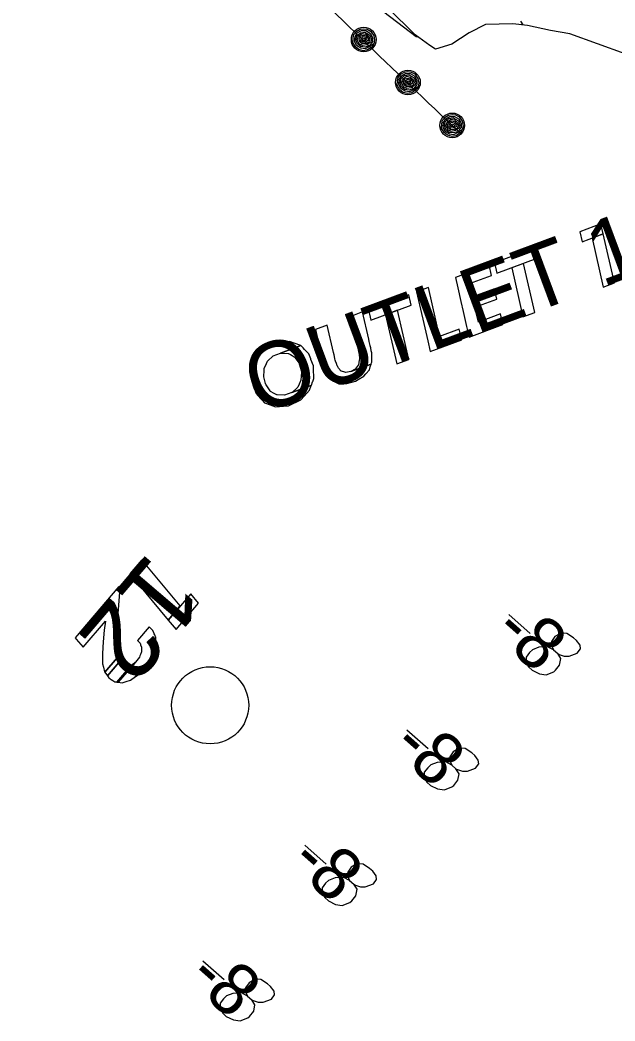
# Model space of a CAD drawing. Extents: x 3962991 to 3983549, y 181631 to 204078.
# Drawn here: x 3977570 to 3977956, y 190147 to 190796 of the extents above; entities that cross this region are included whole.
import ezdxf

# ---------------------------------------------------------------- set-up
doc = ezdxf.new("R2010")
doc.units = 0
for name, color, linetype in [('V-ANNO-MASK', 7, 'Continuous'), ('V-ANNO-MASK2', 7, 'Continuous'), ('V-RIVR-EDGE', 7, 'Continuous'), ('V-RIVR-IDEN', 7, 'Continuous'), ('V-RIVR-MILE', 7, 'Continuous'), ('V-RIVR-RANG', 7, 'Continuous'), ('V-RRAP-FSHR', 7, 'Continuous'), ('V-WETL-SWMP', 7, 'Continuous')]:
    doc.layers.add(name, color=color, linetype=linetype)

msp = doc.modelspace()

# ---------------------------------------------------------------- linework, layer by layer
at = {"layer": 'V-ANNO-MASK2'}
for p, q in [((3977887.31, 190410.64), (3977901.14, 190398.41)), ((3977821.27, 190335.95), (3977835.1, 190323.72)), ((3977755.04, 190261.03), (3977768.87, 190248.8)), ((3977688.8, 190186.11), (3977702.64, 190173.88))]:
    msp.add_line(p, q, dxfattribs=at)
for points in [[(3977933.53, 190659.01), (3977935.02, 190652.5), (3977948.62, 190657.56), (3977947.13, 190664.07)], [(3977941.36, 190654.87), (3977948.64, 190623.08), (3977955.89, 190625.78), (3977948.62, 190657.56)], [(3977878.15, 190638.82), (3977879.69, 190632.05), (3977905.84, 190641.77), (3977904.29, 190648.55)], [(3977859.98, 190597.52), (3977861.55, 190590.68), (3977883.45, 190598.83), (3977881.88, 190605.66), (3977867.62, 190600.36), (3977865.4, 190610), (3977879.67, 190615.31), (3977878.14, 190621.98), (3977863.87, 190616.67), (3977861.88, 190625.37), (3977876.15, 190630.68), (3977874.59, 190637.5), (3977852.69, 190629.35), (3977854.25, 190622.53), (3977856.24, 190613.83), (3977857.77, 190607.16)], [(3977889.24, 190635.6), (3977896.56, 190603.71), (3977904.27, 190606.58), (3977896.96, 190638.47)], [(3977796.37, 190608.4), (3977797.92, 190601.63), (3977824.06, 190611.36), (3977822.52, 190618.13)], [(3977834.79, 190588.2), (3977836.38, 190581.32), (3977856.83, 190588.93), (3977855.25, 190595.81), (3977842.5, 190591.07), (3977835.23, 190622.85), (3977827.52, 190619.99)], [(3977787.71, 190569.92), (3977784.87, 190568.26), (3977798.13, 190573.19), (3977798.36, 190573.88), (3977798.37, 190573.91), (3977798.55, 190574.44), (3977798.54, 190575.85), (3977798.55, 190575.97), (3977798.54, 190576.01), (3977798.53, 190578.67), (3977798.53, 190579.53), (3977798.53, 190579.78), (3977798.41, 190580.37), (3977798.12, 190581.85), (3977798.11, 190581.85), (3977797.76, 190583.61), (3977797.62, 190584.28), (3977797.46, 190585.07), (3977797.44, 190585.2), (3977796.86, 190587.73), (3977796.51, 190589.26), (3977792.46, 190606.95), (3977784.8, 190604.1), (3977788.8, 190586.4), (3977789.15, 190584.86), (3977789.71, 190582.32), (3977789.73, 190582.2), (3977789.9, 190581.4), (3977790.06, 190580.74), (3977790.27, 190578.93), (3977790.45, 190577.41), (3977790.52, 190576.8), (3977790.55, 190576.57), (3977790.36, 190575.63), (3977789.79, 190572.75), (3977789.78, 190572.71), (3977789.66, 190572.54), (3977788.29, 190570.62), (3977787.85, 190569.99)], [(3977807.47, 190605.18), (3977814.78, 190573.29), (3977822.5, 190576.16), (3977815.19, 190608.06)], [(3977782.34, 190560.46), (3977787.86, 190562.15), (3977789.71, 190563.21), (3977793.23, 190565.21), (3977794.65, 190566.87), (3977796.89, 190569.5), (3977797.51, 190571.35), (3977798.13, 190573.19), (3977784.87, 190568.26), (3977781.65, 190567.66), (3977781.61, 190567.67), (3977780.92, 190567.88), (3977778.81, 190568.51), (3977778.72, 190568.59), (3977778.7, 190568.63), (3977776.77, 190570.57), (3977776.44, 190571.32), (3977776.35, 190571.53), (3977776.1, 190572.07), (3977775.5, 190573.44), (3977775, 190575.14), (3977774.81, 190575.79), (3977774.59, 190576.57), (3977774.56, 190576.69), (3977773.99, 190579.22), (3977773.63, 190580.76), (3977769.59, 190598.44), (3977761.88, 190595.57), (3977765.93, 190577.89), (3977766.29, 190576.36), (3977766.91, 190573.84), (3977766.94, 190573.72), (3977767.13, 190572.93), (3977767.32, 190572.28), (3977767.81, 190570.58), (3977768.23, 190569.15), (3977768.49, 190568.6), (3977768.59, 190568.4), (3977768.94, 190567.66), (3977770.03, 190565.4), (3977770.05, 190565.37), (3977770.14, 190565.28), (3977771.12, 190564.23), (3977771.43, 190563.89), (3977771.45, 190563.87), (3977771.87, 190563.43), (3977772.99, 190562.23), (3977774.96, 190561.34), (3977777.16, 190560.37), (3977780.37, 190560.42)], [(3977741.27, 190545.83), (3977744.35, 190546.09), (3977752.43, 190549.97), (3977754.51, 190552.27), (3977758.02, 190556.13), (3977759.23, 190559.36), (3977746.65, 190554.68), (3977741.83, 190552.94), (3977737.02, 190553.14), (3977736.91, 190553.19), (3977735.08, 190554.18), (3977735.07, 190554.18), (3977732.74, 190555.43), (3977732.52, 190555.74), (3977731.62, 190557.06), (3977729.89, 190559.59), (3977729.82, 190559.87), (3977729.81, 190559.87), (3977729.62, 190560.56), (3977728.45, 190564.79), (3977728.45, 190564.79), (3977728.43, 190564.87), (3977728.45, 190565.16), (3977728.65, 190568.98), (3977728.72, 190570.29), (3977728.73, 190570.32), (3977730.14, 190573.53), (3977730.79, 190575), (3977730.82, 190575.07), (3977734.54, 190578.46), (3977734.57, 190578.49), (3977739.35, 190580.3), (3977752.43, 190585.16), (3977748.21, 190586.74), (3977745.17, 190587.88), (3977739.57, 190587.39), (3977737.05, 190587.18), (3977737.05, 190587.18), (3977729.28, 190583.57), (3977726.87, 190581.07), (3977723.47, 190577.54), (3977722.06, 190573.86), (3977722.04, 190573.83), (3977722.04, 190573.81), (3977721.14, 190571.47), (3977721.11, 190571.4), (3977720.56, 190569.96), (3977720.55, 190567.27), (3977720.55, 190567.24), (3977720.55, 190565.97), (3977720.54, 190562.22), (3977720.53, 190561.93), (3977720.54, 190561.85), (3977722.02, 190557.73), (3977722.26, 190557.06), (3977722.37, 190556.79), (3977723.38, 190554), (3977724.51, 190552.76), (3977724.79, 190552.47), (3977726.24, 190550.89), (3977727.4, 190549.65), (3977727.46, 190549.58), (3977728.83, 190548.11), (3977728.9, 190548.08), (3977732.59, 190546.67), (3977735.98, 190545.38)], [(3977746.75, 190554.77), (3977746.65, 190554.68), (3977759.23, 190559.36), (3977759.26, 190559.43), (3977759.25, 190559.42), (3977760.11, 190561.73), (3977760.16, 190561.84), (3977760.15, 190561.84), (3977760.88, 190563.78), (3977760.82, 190565.87), (3977760.81, 190566.26), (3977760.8, 190566.26), (3977760.76, 190567.9), (3977760.66, 190571.03), (3977760.65, 190571.34), (3977760.63, 190572.09), (3977759.03, 190576.17), (3977759, 190576.24), (3977758.91, 190576.49), (3977757.63, 190579.76), (3977756.73, 190580.7), (3977756.71, 190580.72), (3977754.81, 190582.71), (3977753.94, 190583.62), (3977753.9, 190583.66), (3977752.49, 190585.14), (3977752.47, 190585.15), (3977752.43, 190585.16), (3977739.35, 190580.3), (3977739.42, 190580.29), (3977739.45, 190580.29), (3977744.3, 190580.08), (3977744.43, 190580.08), (3977745.72, 190579.32), (3977748.54, 190577.68), (3977748.56, 190577.66), (3977749.26, 190576.65), (3977751.34, 190573.67), (3977751.41, 190573.41), (3977751.43, 190573.34), (3977752.6, 190569.1), (3977752.79, 190568.41), (3977752.77, 190568.1), (3977752.61, 190564.87), (3977752.54, 190563.19), (3977752.34, 190562.72), (3977751.27, 190560.21), (3977750.44, 190558.23), (3977750.27, 190558.07)], [(3977674.16, 190416.26), (3977649.18, 190446.27), (3977641.41, 190437.16), (3977666.39, 190407.15)], [(3977635.14, 190427.95), (3977634.41, 190428.97), (3977605.96, 190395.65), (3977606.75, 190394.71), (3977611.12, 190389.46), (3977625.64, 190406.47), (3977624.75, 190400.46), (3977624.12, 190392.97), (3977623.72, 190385.36), (3977623.74, 190384.25), (3977623.82, 190380.17), (3977623.85, 190378.8), (3977624.4, 190376.57), (3977625.11, 190373.61), (3977625.32, 190373.29), (3977633.28, 190382.62), (3977633.22, 190383.1), (3977632.79, 190386.4), (3977632.78, 190389.26), (3977632.76, 190390.64), (3977632.94, 190395.02), (3977633.03, 190396.27), (3977633.54, 190404.01), (3977634.03, 190411.33), (3977634.39, 190416.72)], [(3977686.08, 190418.08), (3977680.97, 190424.23), (3977666.39, 190407.15), (3977671.5, 190401)], [(3977654.12, 190402.7), (3977654.09, 190402.73), (3977646.53, 190393.88), (3977646.56, 190393.85), (3977647.51, 190392.72), (3977647.52, 190392.73), (3977648.11, 190392.02), (3977648.35, 190391.46), (3977648.52, 190391.06), (3977649.11, 190389.63), (3977649.09, 190388.43), (3977649.06, 190387.49), (3977649.04, 190386.53), (3977648.34, 190384.69), (3977648.07, 190383.98), (3977647.72, 190383.05), (3977645.13, 190379.74), (3977634.03, 190366.74), (3977636.49, 190366.4), (3977639.08, 190367.22), (3977642.03, 190368.15), (3977645.26, 190370.44), (3977656.58, 190383.7), (3977657.32, 190386.06), (3977658.57, 190390.04), (3977658.48, 190392.16), (3977658.35, 190395.21), (3977658.34, 190395.48), (3977658.31, 190395.97), (3977658.2, 190396.23), (3977657.9, 190396.9), (3977657.62, 190397.52), (3977657.35, 190398.11), (3977657.01, 190398.87), (3977656.38, 190400.26), (3977656.11, 190400.55), (3977655.74, 190400.96), (3977655.12, 190401.63)], [(3977653.78, 190379.39), (3977656.58, 190383.69), (3977645.26, 190370.44), (3977647.48, 190372.01), (3977652.44, 190377.33), (3977652.45, 190377.34)], [(3977634.38, 190379.66), (3977633.28, 190382.61), (3977625.32, 190373.29), (3977626.93, 190370.93), (3977626.96, 190370.9), (3977634.41, 190379.61)], [(3977635.44, 190378.58), (3977634.4, 190379.61), (3977626.96, 190370.9), (3977627.81, 190369.65), (3977628.57, 190369.14), (3977629.02, 190368.83), (3977629.35, 190368.6), (3977629.35, 190368.61), (3977630.5, 190367.83), (3977631.13, 190367.4), (3977631.62, 190367.06), (3977632.33, 190366.97), (3977633.12, 190366.86), (3977642.21, 190377.51), (3977641.1, 190377.24), (3977640.1, 190377), (3977639.12, 190376.76), (3977638.33, 190377), (3977636.89, 190377.43), (3977636.47, 190377.55), (3977636.09, 190377.94)], [(3977643.19, 190378.25), (3977642.2, 190377.5), (3977633.12, 190366.87), (3977633.42, 190366.82), (3977633.82, 190366.77), (3977634.03, 190366.74), (3977645.14, 190379.75), (3977644.44, 190379.21)]]:
    msp.add_lwpolyline(points, close=True, dxfattribs=at)
for points in [[(3977916.37, 190387.77), (3977919.14, 190385.32), (3977920.1, 190384.82), (3977923.35, 190383.71), (3977926.52, 190383.72), (3977931.82, 190385.73), (3977933.89, 190388.47), (3977933.56, 190390.88), (3977931.32, 190393.92), (3977929.34, 190395.66), (3977925.06, 190398.39), (3977922.43, 190398.6), (3977919.5, 190397.68), (3977917.33, 190396.42), (3977915.11, 190393.11), (3977914.85, 190391.22), (3977916.37, 190387.77), (3977912.51, 190389.77), (3977906.93, 190389.43), (3977902.72, 190387.86), (3977900.78, 190386.06), (3977898.53, 190383.12), (3977898.56, 190379.57), (3977900.23, 190376.68), (3977902.61, 190374.59), (3977907.23, 190372.25), (3977911.57, 190371.59), (3977916.5, 190373.57), (3977917.74, 190374.58), (3977920.34, 190377.92), (3977921.21, 190382.08), (3977919.14, 190385.32)], [(3977850.34, 190313.07), (3977853.1, 190310.62), (3977854.07, 190310.12), (3977857.31, 190309.01), (3977860.49, 190309.02), (3977865.78, 190311.03), (3977867.86, 190313.77), (3977867.52, 190316.18), (3977865.28, 190319.22), (3977863.3, 190320.97), (3977859.03, 190323.7), (3977856.4, 190323.91), (3977853.46, 190322.98), (3977851.3, 190321.73), (3977849.07, 190318.41), (3977848.81, 190316.53), (3977850.34, 190313.07), (3977846.47, 190315.08), (3977840.89, 190314.73), (3977836.69, 190313.17), (3977834.74, 190311.36), (3977832.49, 190308.42), (3977832.53, 190304.87), (3977834.2, 190301.99), (3977836.57, 190299.89), (3977841.2, 190297.56), (3977845.54, 190296.89), (3977850.46, 190298.88), (3977851.71, 190299.89), (3977854.3, 190303.22), (3977855.17, 190307.39), (3977853.1, 190310.62)], [(3977784.1, 190238.15), (3977786.87, 190235.7), (3977787.83, 190235.2), (3977791.08, 190234.09), (3977794.25, 190234.1), (3977799.55, 190236.11), (3977801.62, 190238.85), (3977801.29, 190241.26), (3977799.05, 190244.3), (3977797.07, 190246.05), (3977792.79, 190248.78), (3977790.16, 190248.99), (3977787.23, 190248.06), (3977785.06, 190246.81), (3977782.84, 190243.49), (3977782.58, 190241.61), (3977784.1, 190238.15), (3977780.24, 190240.16), (3977774.65, 190239.81), (3977770.45, 190238.25), (3977768.51, 190236.44), (3977766.26, 190233.5), (3977766.29, 190229.95), (3977767.96, 190227.07), (3977770.34, 190224.97), (3977774.96, 190222.64), (3977779.3, 190221.97), (3977784.23, 190223.96), (3977785.47, 190224.97), (3977788.07, 190228.3), (3977788.94, 190232.47), (3977786.87, 190235.7)], [(3977717.87, 190163.23), (3977720.63, 190160.78), (3977721.6, 190160.28), (3977724.84, 190159.17), (3977728.02, 190159.18), (3977733.32, 190161.19), (3977735.39, 190163.93), (3977735.05, 190166.34), (3977732.81, 190169.38), (3977730.84, 190171.13), (3977726.56, 190173.86), (3977723.93, 190174.07), (3977720.99, 190173.14), (3977718.83, 190171.89), (3977716.6, 190168.57), (3977716.35, 190166.69), (3977717.87, 190163.23), (3977714.01, 190165.24), (3977708.42, 190164.89), (3977704.22, 190163.33), (3977702.27, 190161.52), (3977700.03, 190158.58), (3977700.06, 190155.03), (3977701.73, 190152.15), (3977704.1, 190150.05), (3977708.73, 190147.72), (3977713.07, 190147.05), (3977717.99, 190149.04), (3977719.24, 190150.05), (3977721.84, 190153.38), (3977722.7, 190157.55), (3977720.63, 190160.78)]]:
    msp.add_lwpolyline(points, dxfattribs=at)
at = {"layer": 'V-RIVR-EDGE'}
msp.add_lwpolyline([(3977597.25, 191003.12), (3977596.69, 190992.64), (3977667.63, 190915.78), (3977777, 190824.15), (3977827.25, 190785.72), (3977828.42, 190785.4)], dxfattribs=at)
at = {"layer": 'V-RIVR-MILE'}
msp.add_circle((3977693.61, 190351.82), 25, dxfattribs=at)
at = {"layer": 'V-RRAP-FSHR'}
for points in [[(3977799.76, 190780.4), (3977798.4, 190778.83), (3977795.74, 190776.92), (3977793.2, 190776.45), (3977790.08, 190777.23), (3977787.97, 190778.99), (3977786.23, 190781.82), (3977786.43, 190784.72), (3977786.81, 190786.96), (3977788.68, 190789.1), (3977790.88, 190790.36), (3977793.21, 190790.71), (3977795.41, 190790.41), (3977797.7, 190789.16), (3977799.73, 190786.34), (3977800.28, 190783.2), (3977799.75, 190780.85), (3977796.78, 190778.97), (3977794.14, 190777.62), (3977791.38, 190778.05), (3977788.64, 190779.77), (3977787.33, 190782.58), (3977787.6, 190785.59), (3977789.03, 190787.99), (3977791.72, 190789.5), (3977794.7, 190789.47), (3977797.62, 190787.65), (3977798.97, 190784.83), (3977798.99, 190782.04), (3977796.71, 190779.57), (3977794.08, 190778.74), (3977791.26, 190779.11), (3977789.1, 190780.83), (3977788.21, 190783.32), (3977788.69, 190786.04), (3977791.06, 190788.11), (3977793.86, 190788.56), (3977797.2, 190786.59), (3977798.22, 190783.93), (3977797.83, 190782.07), (3977795.36, 190780.27), (3977792.53, 190779.71), (3977790.36, 190780.83), (3977789.08, 190783.58), (3977789.83, 190785.83), (3977792.32, 190787.65), (3977794.69, 190787.19), (3977796.54, 190785.61), (3977797.31, 190783.59), (3977796.41, 190781.73), (3977794.56, 190781), (3977792.27, 190780.78), (3977790.69, 190782.14), (3977790.21, 190784.04), (3977791.25, 190785.96), (3977793.06, 190786.56), (3977794.77, 190786.09), (3977796.12, 190784.34), (3977796.02, 190783.01), (3977794.29, 190781.99), (3977792.37, 190781.9), (3977791.32, 190782.88), (3977791.48, 190784.43), (3977792.85, 190785.71), (3977794.41, 190785.22), (3977795.09, 190784.07), (3977794.03, 190782.81), (3977792.4, 190782.93), (3977792.36, 190784.11), (3977793.41, 190784.56), (3977794.14, 190784.14), (3977793.23, 190783.63)], [(3977828.48, 190752.56), (3977827.12, 190750.99), (3977824.46, 190749.08), (3977821.92, 190748.61), (3977818.81, 190749.39), (3977816.69, 190751.15), (3977814.95, 190753.98), (3977815.15, 190756.88), (3977815.53, 190759.12), (3977817.4, 190761.26), (3977819.59, 190762.52), (3977821.93, 190762.86), (3977824.12, 190762.57), (3977826.42, 190761.32), (3977828.45, 190758.49), (3977829, 190755.36), (3977828.47, 190753.01), (3977825.5, 190751.12), (3977822.85, 190749.78), (3977820.1, 190750.21), (3977817.36, 190751.93), (3977816.05, 190754.74), (3977816.32, 190757.75), (3977817.75, 190760.15), (3977820.44, 190761.66), (3977823.42, 190761.62), (3977826.34, 190759.81), (3977827.69, 190756.99), (3977827.71, 190754.2), (3977825.43, 190751.72), (3977822.8, 190750.9), (3977819.98, 190751.27), (3977817.82, 190752.99), (3977816.93, 190755.48), (3977817.41, 190758.2), (3977819.77, 190760.26), (3977822.58, 190760.72), (3977825.92, 190758.75), (3977826.94, 190756.09), (3977826.55, 190754.22), (3977824.08, 190752.43), (3977821.25, 190751.87), (3977819.08, 190752.99), (3977817.8, 190755.74), (3977818.55, 190757.99), (3977821.04, 190759.81), (3977823.41, 190759.35), (3977825.25, 190757.76), (3977826.03, 190755.75), (3977825.13, 190753.89), (3977823.28, 190753.16), (3977820.98, 190752.94), (3977819.41, 190754.3), (3977818.93, 190756.2), (3977819.97, 190758.11), (3977821.79, 190758.72), (3977823.49, 190758.25), (3977824.84, 190756.49), (3977824.74, 190755.17), (3977823.01, 190754.15), (3977821.09, 190754.06), (3977820.04, 190755.03), (3977820.2, 190756.59), (3977821.57, 190757.87), (3977823.13, 190757.38), (3977823.81, 190756.23), (3977822.75, 190754.97), (3977821.12, 190755.09), (3977821.08, 190756.27), (3977822.13, 190756.72), (3977822.86, 190756.3), (3977821.95, 190755.79)], [(3977857.2, 190724.72), (3977855.84, 190723.14), (3977853.18, 190721.24), (3977850.64, 190720.77), (3977847.52, 190721.55), (3977845.41, 190723.31), (3977843.67, 190726.14), (3977843.87, 190729.04), (3977844.25, 190731.28), (3977846.12, 190733.42), (3977848.31, 190734.68), (3977850.65, 190735.02), (3977852.85, 190734.73), (3977855.14, 190733.48), (3977857.17, 190730.65), (3977857.72, 190727.52), (3977857.19, 190725.17), (3977854.22, 190723.28), (3977851.57, 190721.94), (3977848.82, 190722.37), (3977846.08, 190724.09), (3977844.77, 190726.9), (3977845.04, 190729.91), (3977846.47, 190732.31), (3977849.16, 190733.82), (3977852.14, 190733.78), (3977855.06, 190731.97), (3977856.41, 190729.15), (3977856.43, 190726.36), (3977854.15, 190723.88), (3977851.52, 190723.06), (3977848.7, 190723.43), (3977846.54, 190725.15), (3977845.65, 190727.64), (3977846.13, 190730.36), (3977848.49, 190732.42), (3977851.3, 190732.88), (3977854.64, 190730.9), (3977855.66, 190728.25), (3977855.27, 190726.38), (3977852.79, 190724.59), (3977849.97, 190724.02), (3977847.8, 190725.15), (3977846.52, 190727.9), (3977847.27, 190730.15), (3977849.76, 190731.97), (3977852.13, 190731.51), (3977853.98, 190729.92), (3977854.75, 190727.91), (3977853.85, 190726.05), (3977852, 190725.32), (3977849.7, 190725.1), (3977848.13, 190726.46), (3977847.65, 190728.35), (3977848.69, 190730.27), (3977850.5, 190730.88), (3977852.21, 190730.41), (3977853.56, 190728.65), (3977853.46, 190727.33), (3977851.73, 190726.31), (3977849.81, 190726.21), (3977848.76, 190727.19), (3977848.92, 190728.75), (3977850.29, 190730.03), (3977851.85, 190729.54), (3977852.53, 190728.39), (3977851.47, 190727.13), (3977849.84, 190727.25), (3977849.8, 190728.43), (3977850.85, 190728.88), (3977851.58, 190728.46), (3977850.67, 190727.95)]]:
    msp.add_lwpolyline(points, dxfattribs=at)
for centre in [(3977793.21, 190783.67), (3977821.93, 190755.83), (3977850.65, 190727.99)]:
    msp.add_circle(centre, 8, dxfattribs=at)
msp.add_spline([(3977599.23, 191116.63), (3977585.78, 191063.38), (3977577.44, 191020.54), (3977572.43, 190992.91), (3977576.74, 190983.51), (3977645.06, 190923.1), (3977728.7, 190846.21), (3977855.29, 190723.49)], degree=3, dxfattribs=at)
at = {"layer": 'V-WETL-SWMP'}
for p, q in [((3977826.53, 190786.76), (3977808.98, 190804.29)), ((3977872.18, 190793.51), (3977861.58, 190787.97)), ((3977890.01, 190793.82), (3977872.18, 190793.51)), ((3977899.54, 190792.8), (3977890.01, 190793.82)), ((3977894.94, 190795.66), (3977896.57, 190793.12)), ((3977914.45, 190789.5), (3977899.54, 190792.8)), ((3977836.16, 190779.8), (3977826.53, 190786.76)), ((3977861.58, 190787.97), (3977850.41, 190780.64)), ((3977926.97, 190787.34), (3977914.45, 190789.5)), ((3977962.87, 190774.3), (3977926.97, 190787.34)), ((3977839.77, 190777.49), (3977836.16, 190779.8)), ((3977850.41, 190780.64), (3977839.77, 190777.49))]:
    msp.add_line(p, q, dxfattribs=at)

# ---------------------------------------------------------------- texts
at = {"layer": 'V-ANNO-MASK'}
for s, height, rotation, p in [('OUTLET 12.0E', 41.9999, 20.40337, (3977725.56, 190540.1)), ('12', 50, 229.50453, (3977654.44, 190452.42)), ('-8', 33.5, 318.52064, (3977876.12, 190398)), ('-8', 33.5, 318.52064, (3977810.09, 190323.3)), ('-8', 33.5, 318.52064, (3977743.85, 190248.38)), ('-8', 33.5, 318.52064, (3977677.62, 190173.46))]:
    msp.add_text(s, height=height, rotation=rotation, dxfattribs=at).set_placement(p)
at = {"layer": 'V-RIVR-IDEN'}
for s, height, rotation, p in [('OUTLET 12.0E', 41.9999, 20.40337, (3977725.56, 190540.1)), ('12', 50, 229.50453, (3977654.44, 190452.42))]:
    msp.add_text(s, height=height, rotation=rotation, dxfattribs=at).set_placement(p)
at = {"layer": 'V-RIVR-RANG'}
for p in [(3977876.12, 190398), (3977810.09, 190323.3), (3977743.85, 190248.38), (3977677.62, 190173.46)]:
    msp.add_text('-8', height=33.5, rotation=318.52064, dxfattribs=at).set_placement(p)

doc.saveas('drawing.dxf')
